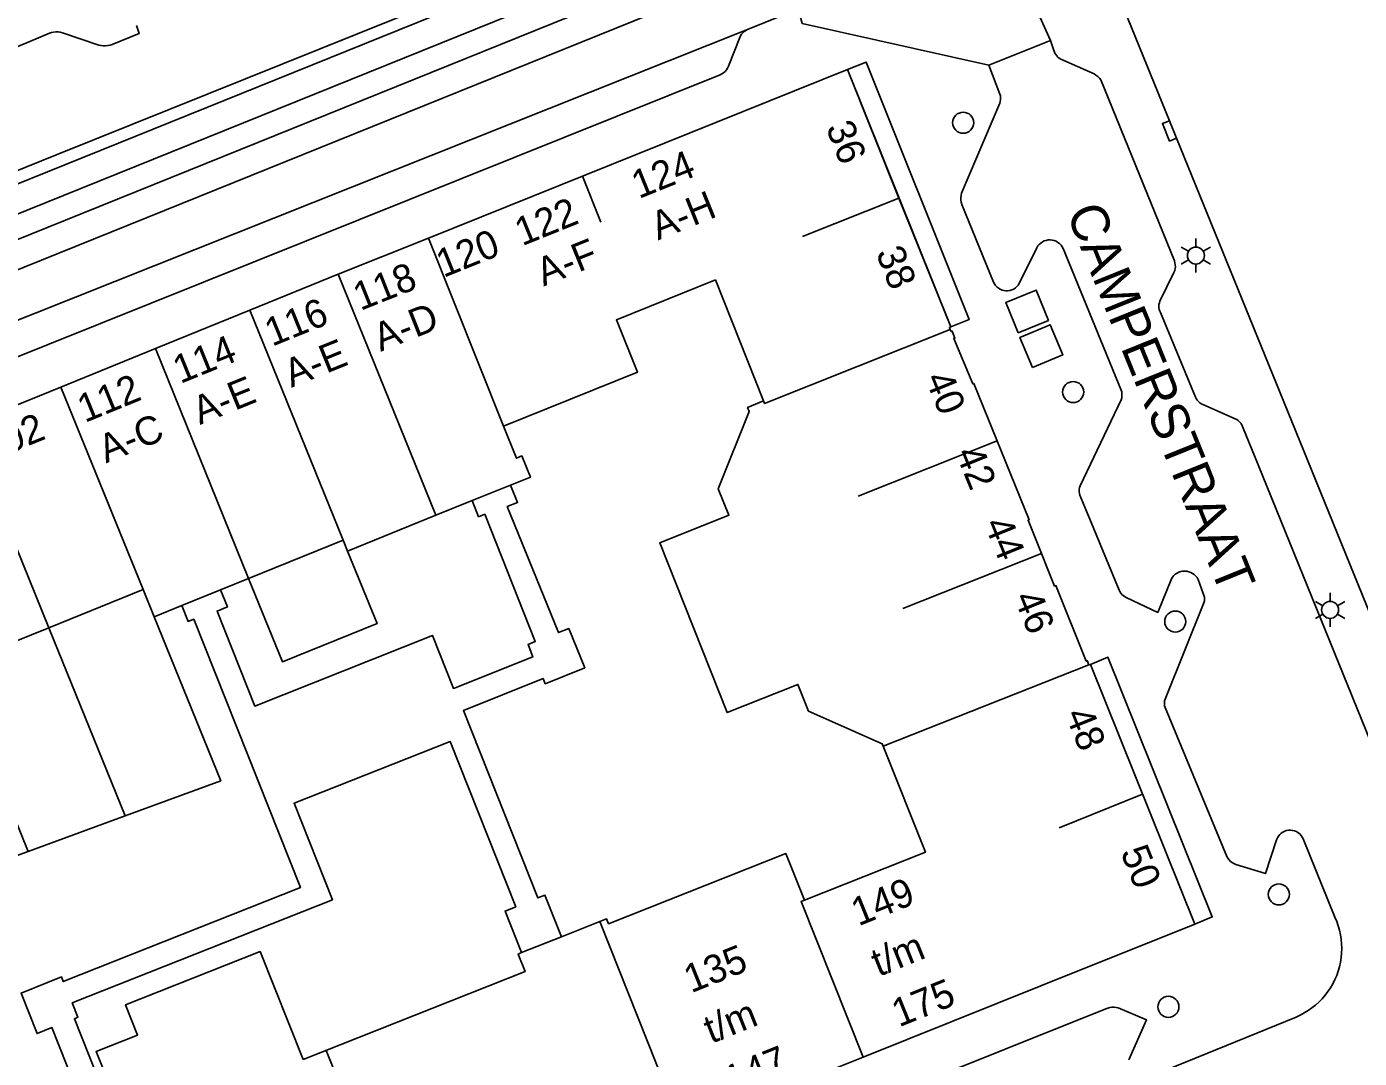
# Model space of a CAD drawing. Extents: x 122462 to 123306, y 485548 to 486417.
# Drawn here: x 122667.6 to 122738.3, y 485638.3 to 485693.1 of the extents above; entities that cross this region are included whole.
import ezdxf

# ---------------------------------------------------------------- set-up
doc = ezdxf.new("R2010")
doc.units = 0
for name, color, linetype in [('B-WE-IE-MEUBILAIR_WEGMEUBILAIR_VERKEERSBORD-S', 7, 'Continuous'), ('Level 1', 7, 'Continuous'), ('Level 10', 7, 'Continuous'), ('Level 17', 7, 'Continuous'), ('Level 19', 7, 'Continuous'), ('Level 37', 7, 'Continuous'), ('Level 4', 7, 'Continuous'), ('Level 40', 7, 'Continuous'), ('Level 42', 7, 'Continuous'), ('Level 50', 7, 'Continuous'), ('Level 53', 7, 'Continuous'), ('N werkgrens', 7, 'Continuous'), ('N-WE-AL-T25', 7, 'Continuous'), ('N-WE-GR-BOOM_DOORWORTELBARE RUIMTE-G', 7, 'Continuous')]:
    doc.layers.add(name, color=color, linetype=linetype)

msp = doc.modelspace()

# ---------------------------------------------------------------- linework, layer by layer
at = {"layer": 'Level 1'}
for p, q in [((122728.234, 485688.129), (122728.611, 485687.203)), ((122688.908, 485681.891), (122684.11, 485679.979)), ((122684.11, 485679.979), (122679.42, 485678.079)), ((122679.42, 485678.079), (122674.4, 485676.039)), ((122674.4, 485676.039), (122669.39, 485673.989)), ((122669.39, 485673.989), (122664.385, 485671.963)), ((122691.223, 485667.961), (122693.259, 485668.786)), ((122689.296, 485667.18), (122691.223, 485667.961)), ((122684.606, 485665.28), (122689.296, 485667.18)), ((122679.349, 485663.828), (122684.37, 485665.862)), ((122684.37, 485665.862), (122684.606, 485665.28)), ((122677.854, 485663.223), (122679.349, 485663.828)), ((122668.74, 485661.212), (122673.746, 485663.24)), ((122673.746, 485663.24), (122674.331, 485661.796)), ((122675.803, 485662.392), (122677.854, 485663.223)), ((122674.331, 485661.796), (122675.803, 485662.392)), ((122663.665, 485659.157), (122668.74, 485661.212)), ((122697.988, 485645.602), (122695.964, 485644.798)), ((122695.964, 485644.798), (122693.839, 485643.954)), ((122702.39, 485634.579), (122711.979, 485638.41))]:
    msp.add_line(p, q, dxfattribs=at)
for points in [[(122756.8, 485709.278), (122725.009, 485696.059), (122728.234, 485688.129)], [(122713.877, 485684.022), (122711.137, 485690.849), (122688.908, 485681.891)], [(122728.611, 485687.203), (122735.346, 485670.641), (122742.08, 485654.079), (122743.749, 485654.76)], [(122716.593, 485677.053), (122716.553, 485677.154), (122716.622, 485677.182), (122713.877, 485684.022)], [(122692.889, 485671.905), (122699.991, 485674.773), (122698.88, 485677.559), (122704.128, 485679.678), (122706.691, 485673.252)], [(122723.96, 485659.232), (122723.867, 485659.463), (122723.815, 485659.442), (122722.21, 485663.446), (122722.141, 485663.418), (122721.084, 485666.038), (122720.729, 485666.917), (122720.787, 485666.94), (122717.855, 485674.185), (122717.791, 485674.159), (122716.787, 485676.561), (122716.848, 485676.585), (122716.7, 485676.958), (122716.64, 485676.934), (122716.593, 485677.053)], [(122706.691, 485673.252), (122705.835, 485672.911), (122705.924, 485672.689), (122704.285, 485668.591), (122704.846, 485667.178), (122701.175, 485665.719), (122704.757, 485656.705), (122708.508, 485658.196), (122709.068, 485656.784), (122712.986, 485655.052), (122713.041, 485654.913)], [(122693.259, 485668.786), (122694.311, 485669.212), (122693.858, 485670.329), (122693.564, 485670.212), (122692.889, 485671.905)], [(122711.979, 485638.41), (122721.4, 485642.198), (122729.582, 485645.476), (122724.039, 485659.264), (122723.96, 485659.232)], [(122713.041, 485654.913), (122715.276, 485649.29), (122708.854, 485646.737)], [(122708.854, 485646.737), (122707.864, 485649.227), (122698.459, 485645.492), (122698.357, 485645.748), (122697.988, 485645.602)], [(122693.839, 485643.954), (122693.655, 485643.881), (122694.024, 485642.952), (122682.238, 485638.273)]]:
    msp.add_lwpolyline(points, dxfattribs=at)
at = {"layer": 'Level 10'}
for points in [[(122716.622, 485677.182), (122711.137, 485690.849), (122712.139, 485691.249), (122717.596, 485677.571), (122716.622, 485677.182)], [(122729.582, 485645.476), (122724.039, 485659.264), (122724.967, 485659.637), (122730.51, 485645.849), (122729.582, 485645.476)]]:
    msp.add_lwpolyline(points, dxfattribs=at)
at = {"layer": 'Level 17'}
for p, q in [((122708.742, 485693.287), (122718.652, 485691.077)), ((122660.23, 485674.806), (122705.834, 485692.97)), ((122718.652, 485691.077), (122721.912, 485692.4))]:
    msp.add_line(p, q, dxfattribs=at)
for points in [[(122709.48, 485702.109), (122709.528, 485702.192), (122709.561, 485702.281), (122709.581, 485702.375), (122709.585, 485702.47), (122709.574, 485702.565), (122709.548, 485702.657), (122709.508, 485702.744), (122709.454, 485702.823), (122709.389, 485702.893), (122709.313, 485702.952), (122709.23, 485702.998), (122709.14, 485703.03), (122709.046, 485703.047), (122708.95, 485703.049), (122704.34, 485700.629), (122693.14, 485695.979), (122669.178, 485686.34), (122636.16, 485672.989), (122614.01, 485664.019), (122548.688, 485637.731), (122544.761, 485636.151)], [(122721.912, 485692.4), (122721.04, 485694.353), (122722.325, 485697.348)], [(122705.834, 485692.97), (122705.839, 485692.972), (122707.667, 485693.722), (122708.537, 485694.018), (122708.742, 485693.287)], [(122660.646, 485689.393), (122667.737, 485692.344), (122668.774, 485692.775), (122668.885, 485692.813), (122669, 485692.837), (122669.118, 485692.848), (122669.235, 485692.845), (122669.351, 485692.828), (122669.465, 485692.797), (122671.397, 485692.152), (122671.516, 485692.123), (122671.637, 485692.108), (122671.759, 485692.107), (122671.881, 485692.12), (122672, 485692.147), (122672.115, 485692.187), (122673.534, 485692.763), (122673.397, 485693.184)], [(122705.834, 485692.97), (122705.743, 485692.926), (122705.658, 485692.869), (122705.583, 485692.802), (122705.517, 485692.725), (122705.463, 485692.639), (122705.421, 485692.547), (122704.821, 485691.022), (122704.775, 485690.924), (122704.716, 485690.834), (122704.645, 485690.752), (122704.563, 485690.68), (122704.473, 485690.62), (122704.376, 485690.573), (122663.22, 485674.061)], [(122721.912, 485692.4), (122722.052, 485692.027), (122722.153, 485691.721), (122722.198, 485691.643), (122722.253, 485691.572), (122722.316, 485691.508), (122722.387, 485691.452), (122722.464, 485691.406), (122724.231, 485690.625), (122724.334, 485690.558), (122724.43, 485690.482), (122724.518, 485690.396), (122724.598, 485690.303), (122728.495, 485680.688), (122728.528, 485680.589), (122728.546, 485680.486), (122728.55, 485680.381), (122728.539, 485680.277), (122728.514, 485680.176), (122728.475, 485680.079), (122727.733, 485678.553), (122727.7, 485678.468), (122727.679, 485678.38), (122727.67, 485678.289), (122727.674, 485678.198), (122727.691, 485678.109), (122727.719, 485678.022), (122727.76, 485677.941), (122729.617, 485673.461), (122729.659, 485673.375), (122729.711, 485673.296), (122729.774, 485673.223), (122729.845, 485673.16), (122729.923, 485673.106), (122730.008, 485673.062), (122731.722, 485672.308), (122731.807, 485672.264), (122731.887, 485672.209), (122731.958, 485672.144), (122732.02, 485672.071), (122732.073, 485671.99), (122732.114, 485671.903), (122732.942, 485669.865), (122739.871, 485652.805)], [(122718.652, 485691.077), (122719.239, 485689.55), (122719.263, 485689.454), (122719.273, 485689.355), (122719.271, 485689.256), (122719.254, 485689.158), (122719.225, 485689.063), (122717.195, 485684.28), (122717.174, 485684.162), (122717.165, 485684.043), (122717.168, 485683.923), (122717.183, 485683.805), (122717.21, 485683.688), (122718.902, 485679.565), (122718.948, 485679.469), (122719.008, 485679.381), (122719.08, 485679.303), (122719.161, 485679.235), (122719.252, 485679.179), (122719.35, 485679.137), (122719.452, 485679.109), (122719.558, 485679.096), (122719.664, 485679.098), (122719.769, 485679.115), (122719.871, 485679.147), (122719.967, 485679.193), (122720.055, 485679.251), (122720.134, 485679.322), (122720.203, 485679.404), (122720.259, 485679.494), (122721.199, 485681.389), (122721.256, 485681.481), (122721.325, 485681.564), (122721.405, 485681.637), (122721.495, 485681.698), (122721.592, 485681.746), (122721.695, 485681.78), (122721.801, 485681.8), (122721.909, 485681.804), (122722.017, 485681.793), (122722.122, 485681.768), (122722.223, 485681.728), (122722.317, 485681.674), (122722.403, 485681.608), (122722.478, 485681.531), (122722.543, 485681.443), (122722.594, 485681.348), (122725.673, 485673.831), (122725.7, 485673.73), (122725.714, 485673.626), (122725.714, 485673.521), (122725.7, 485673.417), (122725.673, 485673.316), (122723.496, 485668.749), (122723.466, 485668.65), (122723.449, 485668.548), (122723.446, 485668.445), (122723.457, 485668.342), (122723.481, 485668.242), (122724.003, 485666.98), (122725.561, 485663.211), (122725.601, 485663.128), (122725.652, 485663.051), (122725.711, 485662.981), (122725.779, 485662.918), (122725.853, 485662.864), (122725.934, 485662.82), (122727.616, 485662.022), (122728.339, 485663.799), (122728.397, 485663.891), (122728.467, 485663.975), (122728.547, 485664.048), (122728.637, 485664.11), (122728.735, 485664.158), (122728.838, 485664.193), (122728.945, 485664.214), (122729.054, 485664.219), (122729.162, 485664.21), (122729.268, 485664.186), (122729.37, 485664.147), (122729.466, 485664.095), (122729.554, 485664.03), (122729.632, 485663.954), (122729.699, 485663.868), (122729.753, 485663.774), (122730.027, 485663.031), (122730.065, 485662.937), (122730.088, 485662.839), (122730.096, 485662.738), (122730.089, 485662.637), (122730.066, 485662.538), (122728.008, 485657.423), (122727.98, 485657.334), (122727.966, 485657.242), (122727.966, 485657.149), (122727.981, 485657.057), (122728.01, 485656.968), (122731.289, 485649.067), (122731.338, 485648.97), (122731.401, 485648.881), (122731.476, 485648.802)], [(122731.476, 485648.802), (122731.562, 485648.735), (122731.657, 485648.681), (122731.758, 485648.641), (122733.328, 485648.155), (122733.927, 485649.949), (122733.968, 485650.048), (122734.023, 485650.14), (122734.09, 485650.224), (122734.169, 485650.297), (122734.257, 485650.358), (122734.354, 485650.406), (122734.456, 485650.439), (122734.561, 485650.458), (122734.669, 485650.461), (122734.775, 485650.45), (122734.879, 485650.423), (122734.978, 485650.381), (122735.07, 485650.326), (122735.153, 485650.258), (122735.226, 485650.179), (122735.287, 485650.09), (122735.334, 485649.994), (122737.019, 485645.834), (122737.115, 485645.609), (122737.196, 485645.379), (122737.263, 485645.144), (122737.315, 485644.906), (122737.353, 485644.664), (122737.376, 485644.421), (122737.383, 485644.177), (122737.375, 485643.933), (122737.353, 485643.69), (122737.315, 485643.449), (122737.263, 485643.21), (122737.195, 485642.975), (122737.114, 485642.745), (122737.018, 485642.521), (122736.909, 485642.302), (122736.786, 485642.091), (122736.651, 485641.888), (122736.503, 485641.693), (122736.343, 485641.509), (122736.172, 485641.334), (122735.991, 485641.17), (122735.8, 485641.018), (122735.6, 485640.878), (122735.392, 485640.75), (122735.176, 485640.636), (122734.954, 485640.535), (122726.998, 485637.288)], [(122726.084, 485638.259), (122727.013, 485640.389), (122725.521, 485641.029), (122725.41, 485641.049), (122725.298, 485641.057), (122725.185, 485641.054), (122725.073, 485641.039), (122724.963, 485641.012), (122724.857, 485640.975), (122714.176, 485636.691)]]:
    msp.add_lwpolyline(points, dxfattribs=at)
at = {"layer": 'Level 19'}
for p, q in [((122672.788, 485651.22), (122668.74, 485661.212)), ((122667.645, 485649.332), (122663.665, 485659.157)), ((122672.788, 485651.22), (122667.645, 485649.332)), ((122667.645, 485649.332), (122662.764, 485647.539))]:
    msp.add_line(p, q, dxfattribs=at)
for points in [[(122695.964, 485644.798), (122695.083, 485647.014), (122694.701, 485646.862), (122690.753, 485656.81), (122694.979, 485658.52), (122695.096, 485658.232), (122697.196, 485659.084), (122696.349, 485661.171), (122695.797, 485660.947), (122693.084, 485667.639), (122693.633, 485667.862), (122693.259, 485668.786)], [(122691.223, 485667.961), (122691.563, 485667.103), (122691.89, 485667.232), (122694.569, 485660.475), (122694.185, 485660.323), (122694.447, 485659.663), (122690.221, 485657.985), (122689.104, 485660.797), (122679.678, 485657.052), (122677.675, 485662.093), (122678.222, 485662.314), (122677.854, 485663.223)], [(122675.803, 485662.392), (122676.141, 485661.543), (122676.442, 485661.663), (122682.099, 485647.412), (122669.514, 485642.417), (122669.416, 485642.664), (122667.268, 485641.812), (122668.122, 485639.66), (122668.91, 485639.973), (122670.094, 485636.991), (122669.52, 485636.763), (122670.367, 485634.635)], [(122674.331, 485661.796), (122677.868, 485653.086), (122672.788, 485651.22)], [(122693.839, 485643.954), (122692.963, 485646.165), (122693.531, 485646.39), (122690.044, 485655.174), (122681.765, 485651.888), (122683.799, 485646.764), (122669.99, 485641.283), (122670.292, 485640.523), (122670.099, 485640.446), (122671.293, 485637.444), (122671.692, 485637.603)]]:
    msp.add_lwpolyline(points, dxfattribs=at)
at = {"layer": 'Level 37'}
for points in [[(122831.695, 485753.286), (122749.349, 485719.414), (122746.888, 485718.394), (122744.433, 485717.362), (122741.982, 485716.318), (122739.537, 485715.262), (122737.097, 485714.193), (122734.663, 485713.112), (122732.234, 485712.019), (122729.811, 485710.913), (122727.393, 485709.796), (122725.051, 485708.714), (122722.702, 485707.646), (122720.348, 485706.592), (122717.987, 485705.55), (122715.621, 485704.523), (122713.249, 485703.509), (122710.871, 485702.509), (122708.487, 485701.522), (122706.098, 485700.549), (122540.465, 485633.647), (122497.591, 485615.701), (122462.03, 485601.437)], [(122832.259, 485751.918), (122749.912, 485718.045), (122747.458, 485717.028), (122745.009, 485715.999), (122742.566, 485714.958), (122740.128, 485713.905), (122737.695, 485712.839), (122735.267, 485711.761), (122732.845, 485710.671), (122730.428, 485709.568), (122728.017, 485708.454), (122725.667, 485707.369), (122723.311, 485706.297), (122720.949, 485705.239), (122718.581, 485704.195), (122716.207, 485703.164), (122713.827, 485702.146), (122711.441, 485701.143), (122709.049, 485700.153), (122706.652, 485699.177), (122541.028, 485632.278), (122498.152, 485614.332), (122462.03, 485599.841)], [(122462.03, 485598.45), (122499.057, 485613.321), (122548.623, 485633.976), (122706.621, 485697.803), (122708.996, 485698.77), (122711.365, 485699.751), (122713.729, 485700.746), (122716.087, 485701.753), (122718.44, 485702.774), (122720.787, 485703.808), (122723.127, 485704.856), (122725.462, 485705.916), (122727.791, 485706.99), (122730.21, 485708.107), (122732.634, 485709.211), (122735.064, 485710.304), (122737.499, 485711.384), (122739.94, 485712.452), (122742.386, 485713.508), (122744.837, 485714.552), (122747.294, 485715.584), (122749.755, 485716.603), (122832.9, 485750.796)], [(122833.463, 485749.428), (122750.317, 485715.234), (122747.862, 485714.217), (122745.413, 485713.189), (122742.969, 485712.148), (122740.53, 485711.095), (122738.096, 485710.029), (122735.667, 485708.952), (122733.244, 485707.863), (122730.827, 485706.761), (122728.414, 485705.648), (122726.078, 485704.571), (122723.735, 485703.506), (122721.387, 485702.455), (122719.033, 485701.418), (122716.672, 485700.394), (122714.306, 485699.383), (122711.935, 485698.385), (122709.557, 485697.401), (122707.175, 485696.431), (122549.185, 485632.607), (122499.617, 485611.951), (122462.03, 485596.856)]]:
    msp.add_lwpolyline(points, dxfattribs=at)
at = {"layer": 'Level 4'}
for p, q in [((122692.889, 485671.905), (122688.908, 485681.891)), ((122689.296, 485667.18), (122684.11, 485679.979)), ((122684.37, 485665.862), (122679.42, 485678.079)), ((122679.349, 485663.828), (122674.4, 485676.039)), ((122673.746, 485663.24), (122669.39, 485673.989)), ((122668.74, 485661.212), (122664.385, 485671.963)), ((122713.041, 485654.913), (122723.96, 485659.232)), ((122702.39, 485634.579), (122697.988, 485645.602))]:
    msp.add_line(p, q, dxfattribs=at)
for points in [[(122716.593, 485677.053), (122706.742, 485673.124), (122706.691, 485673.252)], [(122711.979, 485638.41), (122708.684, 485646.669), (122708.854, 485646.737)]]:
    msp.add_lwpolyline(points, dxfattribs=at)
at = {"layer": 'Level 40'}
msp.add_line((122728.234, 485688.129), (122728.235, 485688.129), dxfattribs=at)
msp.add_lwpolyline([(122728.611, 485687.203), (122728.245, 485687.053), (122727.865, 485687.977), (122728.234, 485688.129)], dxfattribs=at)
at = {"layer": 'Level 42'}
for points in [[(122720.199, 485676.874), (122719.548, 485678.486), (122721.16, 485679.137), (122721.811, 485677.525), (122720.199, 485676.874)], [(122720.968, 485675.028), (122720.301, 485676.63), (122721.903, 485677.297), (122722.57, 485675.695), (122720.968, 485675.028)]]:
    msp.add_lwpolyline(points, dxfattribs=at)
at = {"layer": 'Level 50'}
for p, q in [((122729.638, 485681.423), (122729.638, 485681.873)), ((122729.248, 485681.198), (122728.858, 485681.423)), ((122730.417, 485681.423), (122730.027, 485681.198)), ((122729.248, 485680.748), (122728.858, 485680.523)), ((122729.638, 485680.073), (122729.638, 485680.523)), ((122730.417, 485680.523), (122730.027, 485680.748)), ((122736.373, 485662.38), (122735.983, 485662.605)), ((122736.763, 485662.605), (122736.763, 485663.055)), ((122737.542, 485662.605), (122737.152, 485662.38)), ((122736.373, 485661.93), (122735.983, 485661.705)), ((122737.542, 485661.705), (122737.152, 485661.93)), ((122736.763, 485661.255), (122736.763, 485661.705))]:
    msp.add_line(p, q, dxfattribs=at)
for centre in [(122729.638, 485680.973), (122736.763, 485662.155)]:
    msp.add_circle(centre, 0.45, dxfattribs=at)
at = {"layer": 'Level 53'}
for centre in [(122717.284, 485688.026), (122723.123, 485673.724), (122728.543, 485661.537), (122734.044, 485647.047), (122728.181, 485641.079)]:
    msp.add_circle(centre, 0.56, dxfattribs=at)
at = {"layer": 'N werkgrens'}
for points in [[(122684.606, 485665.28), (122686.166, 485661.429), (122681.145, 485659.395), (122679.349, 485663.828)], [(122671.692, 485637.603), (122671.254, 485638.707), (122673.453, 485639.58), (122672.82, 485641.175), (122679.961, 485644.009), (122682.238, 485638.273)]]:
    msp.add_lwpolyline(points, dxfattribs=at)
at = {"layer": 'N-WE-AL-T25'}
for p, q in [((122697.071, 485685.18), (122698.043, 485682.742)), ((122713.877, 485684.022), (122708.762, 485681.982)), ((122711.71, 485668.202), (122719.089, 485671.135)), ((122714.081, 485662.236), (122721.438, 485665.159)), ((122726.812, 485652.366), (122722.386, 485650.586)), ((122687.542, 485628.617), (122683.468, 485638.761))]:
    msp.add_line(p, q, dxfattribs=at)

# ---------------------------------------------------------------- texts
at = {"layer": 'B-WE-IE-MEUBILAIR_WEGMEUBILAIR_VERKEERSBORD-S'}
for s, rotation, p in [('36', 291.75538, (122709.976, 485687.773)), ('124', 21.98459, (122700.066, 485683.969)), ('122', 21.98459, (122693.869, 485681.463)), ('A-H', 21.98459, (122701.084, 485681.772)), ('120', 21.98459, (122689.692, 485679.78)), ('A-F', 21.98459, (122695.006, 485679.322)), ('38', 291.7571, (122712.63, 485681.12)), ('118', 21.69372, (122685.282, 485678.027)), ('116', 22.05372, (122680.595, 485676.128)), ('A-D', 21.69372, (122686.351, 485675.856)), ('114', 22.11557, (122675.722, 485674.149)), ('A-E', 22.05372, (122681.616, 485673.944)), ('112', 22.25348, (122670.653, 485672.077)), ('A-E', 22.11557, (122676.76, 485671.97)), ('40', 292.04747, (122715.242, 485674.46)), ('102', 22.02048, (122665.555, 485670.01)), ('A-C', 22.25348, (122671.773, 485669.931)), ('42', 292.04747, (122716.863, 485670.485)), ('44', 292.04747, (122718.378, 485666.732)), ('46', 292.04747, (122719.958, 485662.817)), ('48', 291.89913, (122722.68, 485656.613)), ('50', 291.9291, (122725.621, 485649.294)), ('149', 21.8927, (122711.723, 485645.347)), ('135', 21.77669, (122702.84, 485641.794)), ('t/m', 21.8927, (122712.794, 485642.663)), ('175', 21.8927, (122713.878, 485639.983)), ('t/m', 21.77669, (122703.906, 485639.108)), ('147', 21.77669, (122704.984, 485636.426))]:
    msp.add_text(s, height=1.5, rotation=rotation, dxfattribs=at).set_placement(p)
at = {"layer": 'N-WE-GR-BOOM_DOORWORTELBARE RUIMTE-G'}
msp.add_text('CAMPERSTRAAT', height=2, rotation=292.03546, dxfattribs=at).set_placement((122722.737, 485683.262))

doc.saveas('drawing.dxf')
